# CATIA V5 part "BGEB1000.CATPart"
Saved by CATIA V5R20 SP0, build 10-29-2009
Part number: BGEB1000
Revision: 3
Definition: design
Nomenclature: BGEB1000
Source: made
Description: NOT SPECIFIED
Bounding box of the stored display mesh (mm): x -22.885 to 22.885, y -22.885 to 22.885, z -16.002 to 28.448
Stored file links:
  C:\Users\Utente\Desktop\3D files BGEB\BGEB1000.CATPart
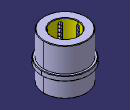
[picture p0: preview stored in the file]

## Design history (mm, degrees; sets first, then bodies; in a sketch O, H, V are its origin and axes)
Body1 "MANIFOLD_SOLID_BREP #38" (main body)
  Solid1: solid without history
Body2 "MANIFOLD_SOLID_BREP #76"
  Solid2: solid without history
Body3 "MANIFOLD_SOLID_BREP #114"
  Solid3: solid without history
Body4 "MANIFOLD_SOLID_BREP #152"
  Solid4: solid without history
Body5 "MANIFOLD_SOLID_BREP #190"
  Solid5: solid without history
Body6 "MANIFOLD_SOLID_BREP #228"
  Solid6: solid without history
Body7 "MANIFOLD_SOLID_BREP #266"
  Solid7: solid without history
Body8 "MANIFOLD_SOLID_BREP #304"
  Solid8: solid without history
Body9 "MANIFOLD_SOLID_BREP #2014"
  Solid9: solid without history
Body10 "MANIFOLD_SOLID_BREP #2052"
  Solid10: solid without history
Body11 "MANIFOLD_SOLID_BREP #2090"
  Solid11: solid without history
Body12 "MANIFOLD_SOLID_BREP #2128"
  Solid12: solid without history
Body13 "MANIFOLD_SOLID_BREP #2166"
  Solid13: solid without history
Body14 "MANIFOLD_SOLID_BREP #2204"
  Solid14: solid without history
Body15 "MANIFOLD_SOLID_BREP #2242"
  Solid15: solid without history
Body16 "MANIFOLD_SOLID_BREP #2280"
  Solid16: solid without history
Body17 "MANIFOLD_SOLID_BREP #2318"
  Solid17: solid without history
Body18 "MANIFOLD_SOLID_BREP #2356"
  Solid18: solid without history
Body19 "MANIFOLD_SOLID_BREP #2394"
  Solid19: solid without history
Body20 "MANIFOLD_SOLID_BREP #2432"
  Solid20: solid without history
Body21 "MANIFOLD_SOLID_BREP #2470"
  Solid21: solid without history
Body22 "MANIFOLD_SOLID_BREP #2508"
  Solid22: solid without history
Body23 "MANIFOLD_SOLID_BREP #2546"
  Solid23: solid without history
Body24 "MANIFOLD_SOLID_BREP #2584"
  Solid24: solid without history
Body25 "MANIFOLD_SOLID_BREP #2622"
  Solid25: solid without history
Body26 "MANIFOLD_SOLID_BREP #2660"
  Solid26: solid without history
Body27 "MANIFOLD_SOLID_BREP #2698"
  Solid27: solid without history
Body28 "MANIFOLD_SOLID_BREP #2736"
  Solid28: solid without history
Body29 "MANIFOLD_SOLID_BREP #2774"
  Solid29: solid without history
Body30 "MANIFOLD_SOLID_BREP #2812"
  Solid30: solid without history
Body31 "MANIFOLD_SOLID_BREP #2850"
  Solid31: solid without history
Body32 "MANIFOLD_SOLID_BREP #2888"
  Solid32: solid without history
Body33 "MANIFOLD_SOLID_BREP #2926"
  Solid33: solid without history
Body34 "MANIFOLD_SOLID_BREP #2964"
  Solid34: solid without history
Body35 "MANIFOLD_SOLID_BREP #3002"
  Solid35: solid without history
Body36 "MANIFOLD_SOLID_BREP #3040"
  Solid36: solid without history
Body37 "MANIFOLD_SOLID_BREP #3078"
  Solid37: solid without history
Body38 "MANIFOLD_SOLID_BREP #3116"
  Solid38: solid without history
Body39 "MANIFOLD_SOLID_BREP #3154"
  Solid39: solid without history
Body40 "MANIFOLD_SOLID_BREP #3192"
  Solid40: solid without history
Body41 "MANIFOLD_SOLID_BREP #3230"
  Solid41: solid without history
Body42 "MANIFOLD_SOLID_BREP #3268"
  Solid42: solid without history
Body43 "MANIFOLD_SOLID_BREP #3306"
  Solid43: solid without history
Body44 "MANIFOLD_SOLID_BREP #3344"
  Solid44: solid without history
Body45 "MANIFOLD_SOLID_BREP #3382"
  Solid45: solid without history
Body46 "MANIFOLD_SOLID_BREP #3420"
  Solid46: solid without history
Body47 "MANIFOLD_SOLID_BREP #3458"
  Solid47: solid without history
Body48 "MANIFOLD_SOLID_BREP #3496"
  Solid48: solid without history
Body49 "MANIFOLD_SOLID_BREP #3534"
  Solid49: solid without history
Body50 "MANIFOLD_SOLID_BREP #3572"
  Solid50: solid without history
Body51 "MANIFOLD_SOLID_BREP #3610"
  Solid51: solid without history
Body52 "MANIFOLD_SOLID_BREP #3648"
  Solid52: solid without history
Body53 "MANIFOLD_SOLID_BREP #3686"
  Solid53: solid without history
Body54 "MANIFOLD_SOLID_BREP #3724"
  Solid54: solid without history
Body55 "MANIFOLD_SOLID_BREP #3762"
  Solid55: solid without history
Body56 "MANIFOLD_SOLID_BREP #3800"
  Solid56: solid without history
Body57 "MANIFOLD_SOLID_BREP #3838"
  Solid57: solid without history
Body58 "MANIFOLD_SOLID_BREP #3876"
  Solid58: solid without history
Body59 "MANIFOLD_SOLID_BREP #3914"
  Solid59: solid without history
Body60 "MANIFOLD_SOLID_BREP #3952"
  Solid60: solid without history
Body61 "MANIFOLD_SOLID_BREP #3990"
  Solid61: solid without history
Body62 "MANIFOLD_SOLID_BREP #4028"
  Solid62: solid without history
Body63 "MANIFOLD_SOLID_BREP #4066"
  Solid63: solid without history
Body64 "MANIFOLD_SOLID_BREP #4104"
  Solid64: solid without history
Body65 "MANIFOLD_SOLID_BREP #4142"
  Solid65: solid without history
Body66 "MANIFOLD_SOLID_BREP #4180"
  Solid66: solid without history
Body67 "MANIFOLD_SOLID_BREP #4218"
  Solid67: solid without history
Body68 "MANIFOLD_SOLID_BREP #4256"
  Solid68: solid without history
Body69 "MANIFOLD_SOLID_BREP #4294"
  Solid69: solid without history
Body70 "MANIFOLD_SOLID_BREP #4332"
  Solid70: solid without history
Body71 "MANIFOLD_SOLID_BREP #4370"
  Solid71: solid without history
Body72 "MANIFOLD_SOLID_BREP #4408"
  Solid72: solid without history
Body73 "MANIFOLD_SOLID_BREP #4446"
  Solid73: solid without history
